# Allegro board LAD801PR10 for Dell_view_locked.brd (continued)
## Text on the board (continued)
User.39: FIGURE | SIZE | 8.0 | 22.0 | 28.0 | 35.0 | 118.0 | 126.0 | 138.0 | 146.0 | 154.0 | 236.0 | 43.0 | 63.0 | 220.0 | 55.0x24.0 | 63.0x24.0 | 63.0x35.0 | 71.0x31.0 | 79.0x31.0 | 126.0x102.0 | 169.0x146.0 | DRILL CHART: TOP to BOTTOM | ALL UNITS ARE IN MILS | TOLERANCE | +3.0/-3.0 | +2.0/-2.0 | PLATED | NON-PLATED | QTY | 5398 | 19 | 18 | 8 | 5 | 1 | 3 | 7 | 4
